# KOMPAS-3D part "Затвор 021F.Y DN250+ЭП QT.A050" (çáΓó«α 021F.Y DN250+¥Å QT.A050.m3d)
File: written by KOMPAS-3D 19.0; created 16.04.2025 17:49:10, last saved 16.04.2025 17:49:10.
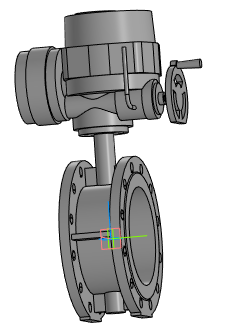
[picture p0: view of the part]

Document properties: Полное имя файла: Затвор 021F.Y DN250+ЭП QT.A050.a3d

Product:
- Part/product: Затвор 021F.Y DN250+ЭП QT.A050
    Масса: 164.705

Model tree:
1. Операция без истории:1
